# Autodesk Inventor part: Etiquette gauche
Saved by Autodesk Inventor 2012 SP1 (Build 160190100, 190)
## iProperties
Created: 2014-12
Part Number: Etiquette gauche
Material: Default
Document SubType Name: Modeling
Designer: Bruno
Density: 1 g/cm^3
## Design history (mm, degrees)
node "Etiquette gauche1"
node "Etiquette gauche"
node "Base1"
